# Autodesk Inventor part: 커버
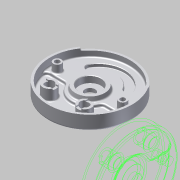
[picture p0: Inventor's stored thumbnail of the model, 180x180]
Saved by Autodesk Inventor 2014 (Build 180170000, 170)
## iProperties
Company: 한국ATC센터
Created: 2015-04
Part Number: 커버
Document SubType Name: Modeling
Designer: KYOUNG IL JANG
Density: 2.71 g/cm^3
Material: 알루미늄-6061
Mass: 1067.78 g
Surface Area: 1019.6 cm^2
Volume: 394.015 cm^3
Appearance: 매끄러움 - 흰색
Author: KYOUNG IL JANG
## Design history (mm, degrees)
sketch "스케치1"
  geometry: L1 (-59, -19)-(-59, 19); L2 (59, 19)-(59, -19); L3 (-41, 19)-(-41, -19); L4 (41, -19)-(41, 19); L5 (38.527, 33.023)-(55.442, 39.179); L6 (-38.527, 33.023)-(-55.442, 39.179); C1 r 90 at (0, 0); C2 r 95 at (0, 0); A1 r 59 centre (0, 19) between (59, 19) and (-59, 19); A2 r 59 centre (0, -19) between (-59, -19) and (59, -19); A3 r 41 centre (0, -19) between (-41, -19) and (41, -19); A4 r 41 centre (0, 19) between (41, 19) and (-41, 19); 2 further points
  constraints: 12 end point, 12 point on circle, 6 centre point, 4 tangent, 2 parallel, 2 point on line, 1 coincident, 1 horizontal alignment, 1 midpoint, 1 vertical, 1 vertical alignment, 3 other
  dimensions: "d2" = 180 diameter of C1; "d3" = 156 dimension on A2 A1; "d4" = 118 distance between parallel lines of L2 L1; "d5" = 18 distance between parallel lines of L2 L4; "d8" = 190 diameter of C2; "d120" = 140 deg angle of L6 L5; "d121" = 110 deg dimension on A1.centre point (0, 0) L5.end
extrude "돌출1" new body sketch "스케치1" distance "d6" = 14; taper "d7" = 0 deg
extrude "돌출2" join sketch "스케치1" distance "d9" = 13; taper "d10" = 0 deg
extrude "돌출3" cut sketch "스케치1" distance "d11" = 7; taper "d12" = 0 deg
sketch "스케치2"
  geometry: C1 r 11.5 at (0, 0); 1 further point
  constraints: 1 centre point, 1 coincident
  dimensions: "d13" = 23 diameter of C1
extrude "돌출4" cut sketch "스케치2" stored distance "d14" = 7; taper "d15" = 0 deg
fillet "모깎기1"
fillet "모깎기2"
sketch "스케치3"
  geometry: L1 (-73.724, 51.622)-(-77.819, 54.49); L2 (73.724, 51.622)-(77.819, 54.49); L3 (0, 0)-(0, -90); A1 r 95 centre (0, 0) between (-77.819, 54.49) and (77.819, 54.49) reference; A2 r 90 centre (0, 0) between (-73.724, 51.622) and (73.724, 51.622) reference; 1 further point
  constraints: 6 end point, 5 point on circle, 1 point on line, 1 vertical, 1 other
  dimensions: "d16" = 250 deg dimension on L2 L1
extrude "돌출5" join sketch "스케치3" distance "d17" = 5; taper "d18" = 0 deg
hole "구멍1" diameter "d21" = 50; stored, may be unused: countersink angle "d25" = 90 deg, drill point angle "d27" = 0 deg; dims "d19" = 10, "d20" = 10, "d22" = 6, "d23" = 4, "d24" = 2, "d26" = 5
fillet "모깎기3" dims "d28" = 0.3
fillet "모깎기5" dims "d30" = 3
sketch "스케치4"
  geometry: C1 r 35 at (0, 0); C2 r 25 at (0, 0); 1 further point
  constraints: 2 centre point, 1 coincident
  dimensions: "d32" = 70 diameter of C1 (derived); "d36" = 10 radial gap between concentric circles of C1 C2
extrude "돌출6" join sketch "스케치4" distance "d33" = 10; taper "d34" = 0 deg
feature "면 기울기2" dims angle "d37" = 10 deg
chamfer "모따기1" distance "d39" = 1; stored, may be unused: second distance "d40" = 2, angle "d41" = 45 deg
fillet "모깎기7" dims "d42" = 5
sketch "스케치5"
  geometry: L1 (-40.249, -12)-(-89.196, -12); L2 (40.249, -12)-(89.196, -12); A1 r 90 centre (0, 0) between (-89.196, -12) and (89.196, -12) reference; A2 r 42 centre (0, 0) between (-40.249, -12) and (40.249, -12); 1 further point
  constraints: 4 end point, 4 point on circle, 1 centre point, 1 collinear, 1 horizontal, 1 point on line
  dimensions: "d43" = 48 radial gap between concentric circles of A1 A2; "d44" = 12 distance from line of point (0, 0) L1
extrude "돌출7" cut sketch "스케치5" stored distance "d45" = 10; taper "d46" = 0 deg
fillet "모깎기8" dims "d47" = 10
chamfer "모따기2" distance "d49" = 1; stored, may be unused: second distance "d50" = 2, angle "d51" = 45 deg
sketch "스케치7"
  geometry: L1 (36.062, 36.062)-(50.912, 50.912); L2 (-36.062, 36.062)-(-50.912, 50.912); A1 r 72 centre (0, 0) between (50.912, 50.912) and (-50.912, 50.912); A2 r 51 centre (0, 0) between (36.062, 36.062) and (-36.062, 36.062); 1 further point
  constraints: 8 point on circle, 4 end point, 2 centre point, 2 point on line, 1 coincident, 1 horizontal alignment
  dimensions: "d54" = 72 radius of A1; "d55" = 21 radial gap between concentric circles of A1 A2; "d56" = 90 deg angle of L2 L1
extrude "돌출8" join sketch "스케치7" distance "d57" = 5; taper "d58" = 0 deg
fillet "모깎기10" dims "d59" = 5
fillet "모깎기11" dims "d60" = 5
fillet "모깎기12" dims "d61" = 3
sketch "스케치6"
  geometry: C1 r 68 at (0, 0); 1 further point
  constraints: 1 centre point, 1 other
  dimensions: "d119" = 136 diameter of C1
feature "엠보싱1" sketch "스케치6" dims "d62" = 0.5, "d63" = 0
sketch "스케치8"
  geometry: C1 r 9 at (74, 0); C2 r 9 at (-74, 0); A1 r 74 centre (0, 0) between (74, 0) and (-74, 0); 1 further point
  constraints: 3 centre point, 2 horizontal alignment, 2 point on circle, 1 coincident, 1 equal radius
  dimensions: "d64" = 18 diameter of C1; "d65" = 148 diameter of A1
extrude "돌출9" join sketch "스케치8" stored distance "d66" = 5; taper "d67" = 0 deg
sketch "스케치11"
  geometry: C1 r 15 at (40, -52); C2 r 15 at (-40, -52); 1 further point
  constraints: 2 centre point, 1 equal radius, 1 horizontal alignment
  dimensions: "d83" = 52 vertical distance of point (0, 0) C1.centre; "d84" = 80 distance of C2.centre C1.centre; "d85" = 40 horizontal distance of point (0, 0) C1.centre (= 0.5 x d84); "d86" = 30 diameter of C1
extrude "돌출10" join sketch "스케치11" stored distance "d87" = 5; taper "d88" = 0 deg
node "구멍3"
node "구멍5"
hole "구멍6" diameter "d93" = 20; stored, may be unused: countersink angle "d97" = 90 deg, drill point angle "d99" = 118 deg; dims "d91" = 10, "d92" = 10, "d94" = 6, "d95" = 4, "d96" = 2, "d98" = 8
hole "구멍7" diameter "d102" = 20; stored, may be unused: countersink angle "d106" = 90 deg, drill point angle "d108" = 118 deg; dims "d100" = 10, "d101" = 10, "d103" = 6, "d104" = 4, "d105" = 2, "d107" = 8
sketch "스케치13"
  geometry: L1 (6, -13.748)-(6, -8); L2 (6, 8)-(6, 13.748); L3 (-6, -13.748)-(-6, -8); L4 (-6, 8)-(-6, 13.748); L5 (-66.252, -6)-(-72, -6); L6 (-88, -6)-(-93.748, -6); L7 (-66.252, 6)-(-72, 6); L8 (-88, 6)-(-93.748, 6); A1 r 15 centre (0, 0) between (6, -13.748) and (6, 13.748) reference; A2 r 10 centre (0, 0) between (6, -8) and (6, 8) reference; A3 r 15 centre (-80, 0) between (-66.252, -6) and (-93.748, -6) reference; A4 r 10 centre (-80, 0) between (-72, -6) and (-88, -6) reference; 1 further point
  constraints: 16 end point, 16 point on circle, 4 equal length, 3 collinear, 2 point on line, 1 perpendicular, 1 vertical
  dimensions: "d109" = 12 distance between parallel lines of L3 L1; "d110" = 6 distance from line of A1.centre L1 (= 0.5 x d109); "d111" = 12 distance between parallel lines of L7 L5; "d112" = 6 distance from line of A3.centre L5 (= 0.5 x d111)
extrude "돌출12" cut sketch "스케치13" distance "d113" = 3; taper "d114" = 0 deg
fillet "모깎기13" dims "d115" = 3
fillet "모깎기14" dims "d116" = 1
node "솔리드1"
sketch "스케치9"
  geometry: 1 further point
hole "구멍2" sketch "스케치9" diameter "d68" = 11; stored, may be unused: countersink angle "d72" = 90 deg, drill point angle "d74" = 0 deg; dims "d69" = 6, "d70" = 18, "d71" = 11, "d73" = 8
sketch "스케치10"
  geometry: 1 further point
hole "구멍4" sketch "스케치10" diameter "d75" = 11; stored, may be unused: countersink angle "d79" = 90 deg, drill point angle "d81" = 0 deg; dims "d76" = 6, "d77" = 18, "d78" = 11, "d80" = 8
